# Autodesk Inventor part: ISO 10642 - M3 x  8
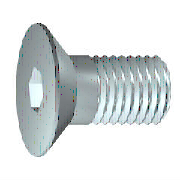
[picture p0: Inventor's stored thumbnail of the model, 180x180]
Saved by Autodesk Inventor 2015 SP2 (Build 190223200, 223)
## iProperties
IsCustomPart: 0
Created: 2012-02
Part Number: ISO 10642 - M3 x  8
Material: Stahl
Description: Innensechskantschraube mit Senkkopf - 1 - Produktklasse A
Document SubType Name: Modeling
Standard: ISO 10642
Designer: Hübner
Standard Revision: Second edition 2004-03-01
Standards Organization: ISO
Language: de-DE
Size Designation: M3 x  8
Categories: <MemberInstance><Categories><Category DisplayName="Verbindungselemente" InternalName="e4da775c-781d-43d5-af7c-5136215cf5a6" Mnemonic="FSTN"><Category DisplayNam
Density: 7.85 g/cm^3
Appearance: Platte
Author: Hübner
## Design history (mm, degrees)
body "Solid1"
revolve "Körper" stored, may be unused: angle "d13" = 90 deg
sketch "Skizze2"
  geometry: L1 (0, -3.878)-(0, 3.878) reference; L2 (-3.878, 0)-(3.878, 0) reference; L3 (1.155, 0)-(0.577, -1); L4 (0.577, -1)-(-0.577, -1); L5 (-0.577, -1)-(-1.155, 0); L6 (-1.155, 0)-(-0.577, 1); L7 (-0.577, 1)-(0.577, 1); L8 (0.577, 1)-(1.155, 0); A1 r 1.155 centre (0, 0) between (0, 1.155) and (1.155, 0) reference; 2 further points
  constraints: 12 end point, 2 coincident, 2 point on circle, 2 point on line, 12 other
extrude "Loch" join sketch "Skizze2" taper "d14" = 0 deg; stored distance "d30" = 10
feature "Gewinde" dims "d15" = 4 (= GEL), "d16" = 0
chamfer "Fase1" distance "d17" = 0.30673 (= -0.5 x SPD + 0.5 x GD); stored, may be unused: second distance "d18" = 0.30673 (= GUL), angle "d39" = 45 deg
workplane "Work Plane1"
sketch "Skizze1"
  geometry: L1 (8, 0)-(8, 1.5); L2 (8, 1.5)-(4, 1.5); L3 (4, 1.5)-(3.693, 1.5); L4 (0, 2.77)-(0, 1.155); L5 (0, 1.155)-(1.3, 1.155); L6 (1.3, 1.155)-(1.967, 0); L7 (1.967, 0)-(8, 0); L8 (0, 2.77)-(0.59, 2.77); L9 (0.59, 2.77)-(1.86, 1.5); L10 (3.693, 1.5)-(1.86, 1.5); L11 (4, 1.5)-(1.86, 1.5); L12 (1.86, 1.5)-(1.86, 1.5); L13 (-1.6, 0)-(9.6, 0) reference; L14 (0, -0.554)-(0, 3.324) reference
  constraints: 24 end point, 4 collinear, 3 parallel
  dimensions: "d0" = 8 distance between parallel lines of L4 L1 (= NLG); "d1" = 4 distance from line of L2.end L1 (= GEL); "d2" = 1.3 distance from line of L5.end L4 (= INTI); "d3" = 3 diameter of L2 L7 (= GD); "d6" = 1.86 distance from line of L9.end L4 (= KOH); "d7" = 45 deg angle of L9 L7 (= 0.5 x SEWI); "d8" = 2.3094 diameter of L5 L7 (= 1.1547 x SW); "d9" = 60 deg angle of L6 L7; "d10" = 5.54 diameter of L8 L7 (= KOD); "d11" = 3 diameter of L10 L7 (= BDM); "d12" = 0.30673 distance of L3.end L2.end (= GAL)
other parameters: "NLG" = 8 [user parameter; used in 1 equation term], "INTI" = 1.3 [user parameter; used in 1 equation term], "GEL" = 4 [user parameter; used in 2 equation terms], "GAL" = 0.30673 (= 0.61345 x PTC) [user parameter; used in 1 equation term], "KOH" = 1.86 [user parameter; used in 1 equation term], "KOD" = 5.54 [user parameter; used in 1 equation term], "GUL" = 0.30673 (= 0.61345 x PTC) [user parameter; used in 1 equation term], "SPD" = 2.38655 (= NND - 1.2269 x PTC) [user parameter; used in 1 equation term], "BDM" = 3 (= NND) [user parameter; used in 1 equation term], "GD" = 3 (= NND) [user parameter; used in 2 equation terms], "SEWI" = 90 deg [user parameter; used in 1 equation term], "d20" = 0, "SW" = 2 [user parameter; used in 1 equation term], "d43" = 0, "d44" = 0, "TOA" = 30 deg [user parameter], "GD1" = 2.38655 (= THREADDIA - 1.2269 x PTC) [user parameter], "EPV" = 3.36 [user parameter], "THREADDIA" = 3 [user parameter; used in 1 equation term], "PTC" = 0.5 [user parameter; used in 5 equation terms], "NND" = 3 [user parameter; used in 3 equation terms], "E0" = 2.31 [user parameter], "THREADDESC" = 12.345 [user parameter]
